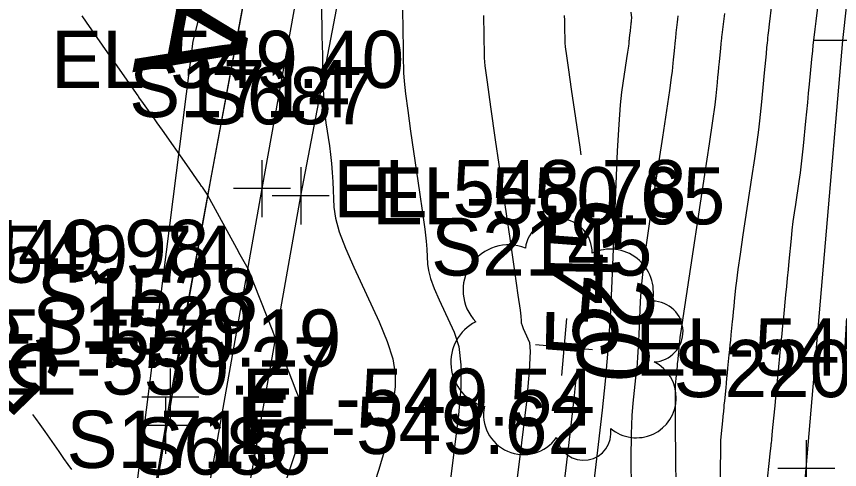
# Model space of a CAD drawing. Extents: x 1724534 to 1727318, y 657156 to 660047.
# Drawn here: x 1725473.7 to 1725531.2, y 659041 to 659072.7 of the extents above; entities that cross this region are included whole.
import ezdxf

# ---------------------------------------------------------------- set-up
doc = ezdxf.new("R2010")
doc.units = 0
for name, color, linetype in [('SURVEY - CENTERLINE - Preliminary', 7, 'Continuous'), ('SURVEY - CONTOURS - Index with Text', 7, 'Continuous'), ('SURVEY - CONTOURS - Intermediate with optional Text', 7, 'Continuous'), ('SURVEY - DTM - Breaklines', 7, 'Continuous'), ('SURVEY - DTM - Breaklines - Points - Elevations', 7, 'Continuous'), ('SURVEY - DTM - Breaklines - Points - Locators', 7, 'Continuous'), ('SURVEY - DTM - Breaklines - Points - Numbers', 7, 'Continuous'), ('SURVEY - ROADSIDE BARRIERS - Points - Elevations', 7, 'Continuous'), ('SURVEY - ROADSIDE BARRIERS - Points - Locators', 7, 'Continuous'), ('SURVEY - ROADSIDE BARRIERS - Points - Numbers', 7, 'Continuous'), ('SURVEY - ROADSIDE BARRIERS with Text', 7, 'Continuous'), ('SURVEY - TRANSPORTATION - Features', 7, 'Continuous'), ('SURVEY - TRANSPORTATION - Features - Points - Elevations', 7, 'Continuous'), ('SURVEY - TRANSPORTATION - Features - Points - Locators', 7, 'Continuous'), ('SURVEY - TRANSPORTATION - Features - Points - Numbers', 7, 'Continuous'), ('SURVEY - TRANSPORTATION - Roads', 7, 'Continuous'), ('SURVEY - TRANSPORTATION - Roads - Points - Elevations', 7, 'Continuous'), ('SURVEY - TRANSPORTATION - Roads - Points - Locators', 7, 'Continuous'), ('SURVEY - TRANSPORTATION - Roads - Points - Numbers', 7, 'Continuous'), ('SURVEY - VEGETATION - Features - Points - Elevations', 7, 'Continuous'), ('SURVEY - VEGETATION - Features - Points - Locators', 7, 'Continuous'), ('SURVEY - VEGETATION - Features - Points - Numbers', 7, 'Continuous'), ('SURVEY - VEGETATION - Features with Text', 7, 'Continuous')]:
    doc.layers.add(name, color=color, linetype=linetype)

msp = doc.modelspace()

# ---------------------------------------------------------------- linework, layer by layer
at = {"layer": 'SURVEY - CENTERLINE - Preliminary'}
for p, q in [((1725498.294, 659119.478), (1725486.022, 659071.007)), ((1725486.022, 659071.007), (1725479.743, 659021.403))]:
    msp.add_line(p, q, dxfattribs=at)
msp.add_arc((1727061.077, 658773.081), 1600, 165.79242, 172.785391, dxfattribs=at)
msp.add_arc((1727061.077, 658773.081), 1600, 165.79242, 172.785391, dxfattribs=at)
msp.add_arc((1727061.077, 658773.081), 1600, 165.79242, 172.785391, dxfattribs=at)
at = {"layer": 'SURVEY - CONTOURS - Index with Text'}
for points in [[(1725529.79, 659074.158), (1725529.578, 659072.412), (1725529.508, 659071.839), (1725529.417, 659071.089), (1725529.415, 659071.07), (1725529.383, 659070.733), (1725529.343, 659070.323), (1725529.288, 659069.752), (1725529.12, 659068.014), (1725529.057, 659067.363), (1725528.994, 659066.714), (1725528.931, 659066.065), (1725528.869, 659065.417), (1725528.702, 659063.692), (1725528.635, 659063.051), (1725528.562, 659062.421), (1725528.482, 659061.803), (1725528.394, 659061.196), (1725528.151, 659059.594), (1725528.063, 659058.993), (1725527.985, 659058.395), (1725527.914, 659057.799), (1725527.852, 659057.204), (1725527.697, 659055.621), (1725527.639, 659055.029), (1725527.581, 659054.438), (1725527.523, 659053.848), (1725527.465, 659053.261), (1725527.312, 659051.696), (1725527.255, 659051.11), (1725527.198, 659050.526), (1725527.141, 659049.943), (1725526.875, 659047.236), (1725526.819, 659046.658), (1725526.706, 659045.508), (1725526.556, 659043.978), (1725526.507, 659043.476), (1725526.472, 659043.115), (1725526.45, 659042.896), (1725526.443, 659042.819), (1725526.441, 659042.803), (1725526.433, 659042.727), (1725526.41, 659042.513), (1725526.372, 659042.16), (1725526.32, 659041.668), (1725526.161, 659040.171)], [(1725511.992, 659072.802), (1725511.994, 659072.683), (1725511.997, 659072.568), (1725512.003, 659072.264), (1725512.005, 659072.151), (1725512.008, 659072.04), (1725512.01, 659071.932), (1725512.012, 659071.827), (1725512.018, 659071.55), (1725512.02, 659071.447), (1725512.022, 659071.346), (1725512.024, 659071.247), (1725512.026, 659071.151), (1725512.032, 659070.896), (1725512.061, 659070.622), (1725512.146, 659069.991), (1725512.286, 659069.003), (1725512.482, 659067.658), (1725513.077, 659063.595), (1725513.142, 659063.062)], [(1725512.859, 659048.092), (1725512.651, 659045.99), (1725512.31, 659042.942), (1725511.296, 659034.288)], [(1725474.819, 659044.884), (1725475.01, 659044.615), (1725475.313, 659044.186), (1725475.659, 659043.696), (1725476.639, 659042.306), (1725476.984, 659041.818), (1725477.284, 659041.394), (1725477.537, 659041.035)]]:
    msp.add_lwpolyline(points, dxfattribs=at)
at = {"layer": 'SURVEY - CONTOURS - Intermediate with optional Text'}
for points in [[(1725494.998, 659073.856), (1725495.036, 659072.036), (1725495.05, 659071.361), (1725495.064, 659070.7), (1725495.078, 659070.053), (1725495.091, 659069.421), (1725495.126, 659067.754), (1725495.148, 659067.132), (1725495.189, 659066.516), (1725495.249, 659065.905), (1725495.328, 659065.299), (1725495.564, 659063.693), (1725495.645, 659063.083), (1725495.711, 659062.457), (1725495.763, 659061.816), (1725495.801, 659061.16), (1725495.882, 659059.389), (1725495.992, 659058.628), (1725496.26, 659057.675), (1725496.687, 659056.529), (1725497.273, 659055.191), (1725499.047, 659051.364), (1725499.616, 659050.004), (1725499.993, 659048.795), (1725500.178, 659047.737), (1725500.171, 659046.829), (1725499.898, 659044.609), (1725499.733, 659043.659), (1725499.446, 659042.473), (1725499.034, 659041.051), (1725498.5, 659039.394)], [(1725526.491, 659073.554), (1725526.326, 659072.199), (1725526.272, 659071.754), (1725526.233, 659071.435), (1725526.21, 659071.241), (1725526.202, 659071.172), (1725526.2, 659071.158), (1725526.193, 659071.089), (1725526.175, 659070.896), (1725526.144, 659070.578), (1725526.101, 659070.135), (1725525.971, 659068.787), (1725525.922, 659068.282), (1725525.873, 659067.778), (1725525.824, 659067.275), (1725525.776, 659066.773), (1725525.646, 659065.434), (1725525.575, 659064.808), (1725525.46, 659063.934), (1725525.3, 659062.811), (1725525.095, 659061.439), (1725524.489, 659057.451), (1725524.286, 659056.098), (1725524.131, 659055.03), (1725524.024, 659054.247), (1725523.965, 659053.749), (1725523.873, 659052.802), (1725523.838, 659052.447), (1725523.803, 659052.093), (1725523.769, 659051.741), (1725523.734, 659051.389), (1725523.643, 659050.453), (1725523.608, 659050.102), (1725523.574, 659049.753), (1725523.54, 659049.404), (1725523.506, 659049.056), (1725523.415, 659048.131), (1725523.381, 659047.784), (1725523.347, 659047.438), (1725523.314, 659047.094), (1725523.28, 659046.75), (1725523.19, 659045.835), (1725523.161, 659045.534), (1725523.14, 659045.318), (1725523.127, 659045.187), (1725523.122, 659045.141), (1725523.121, 659045.131), (1725523.116, 659045.086), (1725523.103, 659044.958), (1725523.08, 659044.747), (1725523.049, 659044.452), (1725522.953, 659043.557), (1725522.924, 659043.07), (1725522.907, 659042.281), (1725522.903, 659041.19), (1725522.911, 659039.797)], [(1725500.67, 659073.18), (1725500.697, 659071.874), (1725500.707, 659071.389), (1725500.717, 659070.915), (1725500.727, 659070.451), (1725500.736, 659069.998), (1725500.761, 659068.802), (1725500.798, 659068.21), (1725500.892, 659067.33), (1725501.042, 659066.163), (1725501.248, 659064.709), (1725501.872, 659060.448), (1725502.079, 659059), (1725502.232, 659057.854), (1725502.331, 659057.008), (1725502.376, 659056.464), (1725502.425, 659055.413), (1725502.49, 659054.962), (1725502.649, 659054.396), (1725502.902, 659053.716), (1725503.25, 659052.922), (1725504.302, 659050.652), (1725504.616, 659049.652), (1725504.768, 659048.355), (1725504.759, 659046.761), (1725504.589, 659044.871), (1725503.918, 659039.433)], [(1725516.639, 659073.049), (1725516.703, 659072.648), (1725516.681, 659072.465), (1725516.672, 659072.397), (1725516.664, 659072.329), (1725516.656, 659072.26), (1725516.647, 659072.192), (1725516.625, 659072.011), (1725516.617, 659071.943), (1725516.601, 659071.808), (1725516.592, 659071.74), (1725516.571, 659071.56), (1725516.558, 659071.458), (1725516.554, 659071.423), (1725516.554, 659071.421), (1725516.553, 659071.412), (1725516.55, 659071.387), (1725516.546, 659071.344), (1725516.541, 659071.286), (1725516.523, 659071.106), (1725516.517, 659071.039), (1725516.51, 659070.972), (1725516.497, 659070.838), (1725516.48, 659070.661), (1725516.462, 659070.52), (1725516.42, 659070.23), (1725516.355, 659069.792), (1725515.999, 659067.445), (1725515.898, 659066.548), (1725515.797, 659065.177), (1725515.694, 659063.334), (1725515.59, 659061.017), (1725515.312, 659054.208), (1725515.193, 659051.73), (1725515.042, 659049.402), (1725514.86, 659047.224), (1725514.646, 659045.196), (1725514.036, 659039.99)], [(1725478.256, 659072.783), (1725478.557, 659072.35), (1725480.053, 659070.203), (1725480.375, 659069.743), (1725480.698, 659069.282), (1725481.561, 659068.054), (1725482.169, 659067.19), (1725482.209, 659067.132), (1725482.21, 659067.132), (1725482.231, 659067.101), (1725482.555, 659066.648), (1725483.015, 659066.005), (1725483.225, 659065.709), (1725483.511, 659065.303), (1725483.872, 659064.788), (1725485.576, 659062.351), (1725485.994, 659061.754), (1725486.298, 659061.319), (1725486.488, 659061.048), (1725486.613, 659060.871), (1725486.637, 659060.837), (1725486.671, 659060.788), (1725486.716, 659060.724), (1725486.771, 659060.645), (1725487.054, 659060.239), (1725489.067, 659056.533), (1725489.315, 659056.077), (1725489.487, 659055.763), (1725489.584, 659055.589), (1725489.859, 659055.106), (1725491.581, 659050.743), (1725491.834, 659050.101), (1725492.052, 659049.549), (1725492.234, 659049.087), (1725492.965, 659047.235), (1725493.084, 659046.935), (1725493.184, 659046.681), (1725493.426, 659046.066), (1725493.661, 659045.471), (1725493.723, 659045.316), (1725493.875, 659044.929), (1725493.858, 659044.603), (1725493.693, 659043.914), (1725493.379, 659042.863), (1725492.918, 659041.449), (1725491.488, 659037.194)], [(1725506.335, 659072.804), (1725506.341, 659072.503), (1725506.357, 659071.712), (1725506.364, 659071.418), (1725506.37, 659071.13), (1725506.375, 659070.849), (1725506.381, 659070.574), (1725506.396, 659069.849), (1725506.449, 659069.287), (1725506.595, 659068.144), (1725506.834, 659066.422), (1725507.168, 659064.118), (1725508.181, 659057.202), (1725508.514, 659054.918), (1725508.753, 659053.25), (1725508.899, 659052.2), (1725508.952, 659051.768), (1725508.967, 659051.437), (1725508.988, 659051.295), (1725509.038, 659051.117), (1725509.117, 659050.903), (1725509.227, 659050.653), (1725509.558, 659049.939), (1725509.616, 659049.299), (1725509.544, 659047.914), (1725509.34, 659045.785), (1725509.006, 659042.912), (1725507.939, 659034.257)], [(1725519.944, 659072.774), (1725519.918, 659072.559), (1725519.892, 659072.345), (1725519.822, 659071.773), (1725519.8, 659071.585), (1725519.783, 659071.45), (1725519.773, 659071.369), (1725519.77, 659071.34), (1725519.766, 659071.305), (1725519.759, 659071.223), (1725519.746, 659071.089), (1725519.672, 659070.333), (1725519.652, 659070.12), (1725519.631, 659069.908), (1725519.611, 659069.695), (1725519.59, 659069.483), (1725519.536, 659068.918), (1725519.478, 659068.471), (1725519.346, 659067.553), (1725519.139, 659066.163), (1725518.858, 659064.302), (1725518.009, 659058.712), (1725517.726, 659056.77), (1725517.514, 659055.136), (1725517.372, 659053.811), (1725517.302, 659052.794), (1725517.208, 659050.494), (1725517.168, 659049.657), (1725517.117, 659048.871), (1725517.055, 659048.136), (1725516.983, 659047.451), (1725516.777, 659045.692), (1725516.712, 659044.821), (1725516.672, 659043.526), (1725516.657, 659041.807), (1725516.667, 659039.664)], [(1725523.191, 659072.949), (1725523.008, 659071.443), (1725522.991, 659071.305), (1725522.985, 659071.245), (1725522.98, 659071.197), (1725522.967, 659071.06), (1725522.945, 659070.834), (1725522.914, 659070.519), (1725522.822, 659069.56), (1725522.787, 659069.201), (1725522.752, 659068.843), (1725522.718, 659068.485), (1725522.683, 659068.128), (1725522.591, 659067.176), (1725522.515, 659066.565), (1725522.358, 659065.446), (1725522.118, 659063.818), (1725521.796, 659061.682), (1725520.509, 659053.202), (1725520.278, 659051.664), (1725520.135, 659050.695), (1725520.079, 659050.294), (1725520.049, 659049.982), (1725520.037, 659049.866), (1725520.026, 659049.749), (1725520.014, 659049.633), (1725520.003, 659049.518), (1725519.973, 659049.21), (1725519.962, 659049.094), (1725519.928, 659048.75), (1725519.898, 659048.446), (1725519.876, 659048.218), (1725519.865, 659048.105), (1725519.854, 659047.992), (1725519.824, 659047.691), (1725519.815, 659047.592), (1725519.808, 659047.521), (1725519.803, 659047.478), (1725519.802, 659047.463), (1725519.802, 659047.46), (1725519.8, 659047.445), (1725519.795, 659047.403), (1725519.746, 659046.942), (1725519.739, 659046.543), (1725519.74, 659045.569), (1725519.75, 659044.02), (1725519.769, 659041.894), (1725519.83, 659035.459)]]:
    msp.add_lwpolyline(points, dxfattribs=at)
at = {"layer": 'SURVEY - DTM - Breaklines'}
msp.add_lwpolyline([(1725525.942, 659009.271), (1725526.399, 659011.158), (1725528.918, 659041.105), (1725531.461, 659071.052), (1725534.8, 659101.37), (1725536.346, 659131.334), (1725539.898, 659161.171), (1725544.971, 659191.09), (1725550.75, 659220.691), (1725554.674, 659250.537), (1725558.308, 659280.317), (1725560.346, 659299.038), (1725563.922, 659328.825), (1725567.992, 659357.481)], dxfattribs=at)
at = {"layer": 'SURVEY - DTM - Breaklines - Points - Locators'}
for p, q in [((1725533.461, 659071.052), (1725529.461, 659071.052)), ((1725528.918, 659043.105), (1725528.918, 659039.105)), ((1725530.918, 659041.105), (1725526.918, 659041.105))]:
    msp.add_line(p, q, dxfattribs=at)
at = {"layer": 'SURVEY - ROADSIDE BARRIERS - Points - Locators'}
for p, q in [((1725493.561, 659062.194), (1725493.561, 659058.194)), ((1725495.561, 659060.194), (1725491.561, 659060.194))]:
    msp.add_line(p, q, dxfattribs=at)
at = {"layer": 'SURVEY - ROADSIDE BARRIERS with Text'}
msp.add_lwpolyline([(1725454.307, 658763.664), (1725456.988, 658788.398), (1725459.975, 658813.106), (1725462.961, 658837.817), (1725466.031, 658862.66), (1725469.198, 658887.437), (1725472.364, 658912.252), (1725475.489, 658936.998), (1725478.578, 658961.799), (1725481.795, 658986.471), (1725485.277, 659011.185), (1725489.239, 659035.685), (1725493.561, 659060.194), (1725498.271, 659084.816), (1725503.177, 659108.92), (1725508.576, 659133.257), (1725514.221, 659157.599), (1725521.221, 659181.564), (1725529.697, 659209.302)], dxfattribs=at)
at = {"layer": 'SURVEY - TRANSPORTATION - Features'}
msp.add_lwpolyline([(1725537.281, 659258.937), (1725530.962, 659234.747), (1725524.817, 659210.531), (1725517.386, 659182.521), (1725511.279, 659158.31), (1725505.645, 659133.966), (1725500.348, 659109.577), (1725495.279, 659085.33), (1725490.855, 659060.693), (1725486.478, 659036.153), (1725482.443, 659011.591), (1725478.797, 658986.889), (1725475.825, 658962.14), (1725472.769, 658937.341), (1725469.208, 658912.632), (1725466.187, 658887.82), (1725463.008, 658863.047)], dxfattribs=at)
at = {"layer": 'SURVEY - TRANSPORTATION - Features - Points - Locators'}
for p, q in [((1725490.855, 659062.693), (1725490.855, 659058.693)), ((1725492.855, 659060.693), (1725488.855, 659060.693))]:
    msp.add_line(p, q, dxfattribs=at)
at = {"layer": 'SURVEY - TRANSPORTATION - Roads'}
msp.add_lwpolyline([(1725501.913, 659132.272), (1725496.037, 659106.962), (1725495.616, 659105.008), (1725492.293, 659089.367), (1725491.93, 659087.402), (1725490.237, 659077.551), (1725489.888, 659075.583), (1725484.442, 659046.101), (1725484.106, 659044.131), (1725480.436, 659022.454), (1725480.115, 659020.482), (1725477.562, 659002.676), (1725474.526, 658980.901), (1725474.261, 658978.921), (1725472.804, 658967.02), (1725471.086, 658953.138), (1725470.348, 658947.189), (1725468.597, 658933.312), (1725467.348, 658923.398), (1725465.675, 658909.512), (1725465.425, 658907.529), (1725464.411, 658899.602), (1725462.646, 658885.729), (1725459.817, 658863.933)], dxfattribs=at)
at = {"layer": 'SURVEY - TRANSPORTATION - Roads - Points - Locators'}
for p, q in [((1725484.442, 659048.101), (1725484.442, 659044.101)), ((1725486.442, 659046.101), (1725482.442, 659046.101)), ((1725484.106, 659046.131), (1725484.106, 659042.131)), ((1725486.106, 659044.131), (1725482.106, 659044.131))]:
    msp.add_line(p, q, dxfattribs=at)
at = {"layer": 'SURVEY - VEGETATION - Features - Points - Locators'}
for p, q in [((1725512.139, 659051.605), (1725511.801, 659047.619)), ((1725509.977, 659049.781), (1725513.963, 659049.443))]:
    msp.add_line(p, q, dxfattribs=at)
at = {"layer": 'SURVEY - VEGETATION - Features with Text'}
msp.add_circle((1725511.93, 659049.747), 0.0978, dxfattribs=at)
for centre, radius, start, end in [((1725511.599, 659056.249), 2.34, 358.26311, 173.26338), ((1725508.087, 659053.581), 3.174, 68.01021, 223.84869), ((1725515.211, 659053.443), 3.016, 348.1042, 114.94987), ((1725518.168, 659050.692), 2.129, 272.81715, 90.13629), ((1725507.254, 659048.539), 3.194, 117.11438, 254.63861), ((1725517.029, 659046.06), 2.798, 230.19848, 63.61817), ((1725509.151, 659044.886), 2.804, 168.06164, 324.85056), ((1725513.337, 659043.612), 1.924, 190.17779, 8.92343)]:
    msp.add_arc(centre, radius, start, end, dxfattribs=at)

# ---------------------------------------------------------------- texts
at = {"layer": 'SURVEY - CENTERLINE - Preliminary'}
msp.add_text('A', height=7.5, rotation=259.28891, dxfattribs=at).set_placement((1725483.034, 659075.389))
at = {"layer": 'SURVEY - CONTOURS - Index with Text'}
for s, rotation, p in [('545', 88.91913, (1725515.694, 659048.8)), ('550', 137.47723, (1725477.297, 659048.154))]:
    msp.add_text(s, height=5, rotation=rotation, dxfattribs=at).set_placement(p)
at = {"layer": 'SURVEY - DTM - Breaklines - Points - Elevations'}
msp.add_text('EL-549.98', height=4, dxfattribs=at).set_placement((1725462.482, 659054.509))
at = {"layer": 'SURVEY - DTM - Breaklines - Points - Numbers'}
msp.add_text('S2203', height=4, dxfattribs=at).set_placement((1725519.63, 659046.105))
at = {"layer": 'SURVEY - ROADSIDE BARRIERS - Points - Elevations'}
msp.add_text('EL-550.65', height=4, dxfattribs=at).set_placement((1725498.561, 659058.194))
at = {"layer": 'SURVEY - ROADSIDE BARRIERS - Points - Numbers'}
for s, p in [('S687', (1725486.225, 659065.194)), ('S686', (1725481.793, 659040.685))]:
    msp.add_text(s, height=4, dxfattribs=at).set_placement(p)
at = {"layer": 'SURVEY - TRANSPORTATION - Features - Points - Elevations'}
for s, p in [('EL-548.78', (1725495.855, 659058.693)), ('EL-549.74', (1725464.259, 659054.109))]:
    msp.add_text(s, height=4, dxfattribs=at).set_placement(p)
at = {"layer": 'SURVEY - TRANSPORTATION - Features - Points - Numbers'}
for s, p in [('S1714', (1725481.567, 659065.693)), ('S1715', (1725477.19, 659041.153))]:
    msp.add_text(s, height=4, dxfattribs=at).set_placement(p)
at = {"layer": 'SURVEY - TRANSPORTATION - Roads - Points - Elevations'}
for s, p in [('EL-549.40', (1725476.114, 659067.737)), ('EL-550.19', (1725471.718, 659048.238)), ('EL-550.27', (1725471.292, 659046.286)), ('EL-549.54', (1725489.442, 659044.101)), ('EL-549.62', (1725489.106, 659042.131))]:
    msp.add_text(s, height=4, dxfattribs=at).set_placement(p)
at = {"layer": 'SURVEY - TRANSPORTATION - Roads - Points - Numbers'}
for s, p in [('S1528', (1725475.107, 659051.101)), ('S1529', (1725474.803, 659049.131))]:
    msp.add_text(s, height=4, dxfattribs=at).set_placement(p)
at = {"layer": 'SURVEY - VEGETATION - Features - Points - Elevations'}
msp.add_text('EL-545.54', height=4, dxfattribs=at).set_placement((1725516.97, 659047.612))
at = {"layer": 'SURVEY - VEGETATION - Features - Points - Numbers'}
msp.add_text('S2145', height=4, dxfattribs=at).set_placement((1725502.682, 659054.612))
at = {"layer": 'SURVEY - VEGETATION - Features with Text'}
msp.add_text('20', height=5, rotation=265.14613, dxfattribs=at).set_placement((1725513.389, 659054.792))

doc.saveas('drawing.dxf')
